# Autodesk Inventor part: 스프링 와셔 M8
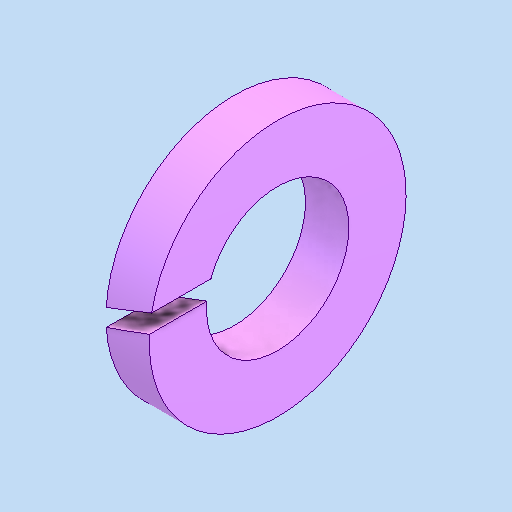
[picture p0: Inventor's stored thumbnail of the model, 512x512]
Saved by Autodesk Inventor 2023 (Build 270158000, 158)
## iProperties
Created: 2024-11
Part Number: 스프링 와셔 M8
Material: 강철, 연강
Description: 스프링 잠금 와셔
Document SubType Name: Modeling
Designer: asung
Density: 7.85 g/cm^3
Appearance: 기본값
Author: jhkim
Sending System: Autodesk Inventor 2025
Preprocessor: ST-DEVELOPER v20
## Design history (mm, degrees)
node "스프링 와셔 M81"
node "솔리드1"
body "Solid1"
